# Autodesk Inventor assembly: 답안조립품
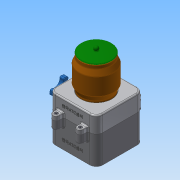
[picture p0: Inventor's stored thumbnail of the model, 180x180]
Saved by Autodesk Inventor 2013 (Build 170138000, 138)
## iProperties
Created: 2018-01
Part Number: 답안조립품
Document SubType Name: Assembly
Designer: Administrator
Author: Administrator
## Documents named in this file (9)
- C:\Users\Administrator\Desktop\480108V1032\답안조립품.iam
- C:\Users\Administrator\Desktop\480108V1032\본체.ipt
- C:\Users\Administrator\Desktop\480108V1032\핸들축.ipt
- C:\Users\Administrator\Desktop\480108V1032\핸들.ipt
- C:\Users\Administrator\Desktop\480108V1032\볼트 M3x12.ipt
- C:\Users\Administrator\Desktop\480108V1032\본체커버.ipt
- C:\Users\Administrator\Desktop\480108V1032\용기.ipt
- C:\Users\Administrator\Desktop\480108V1032\용기캡.ipt
- C:\Users\Administrator\Desktop\480108V1032\볼트 M4x12.ipt
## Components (2 placed, 2 different names)
1. 핸들축:1
2. 핸들:1
